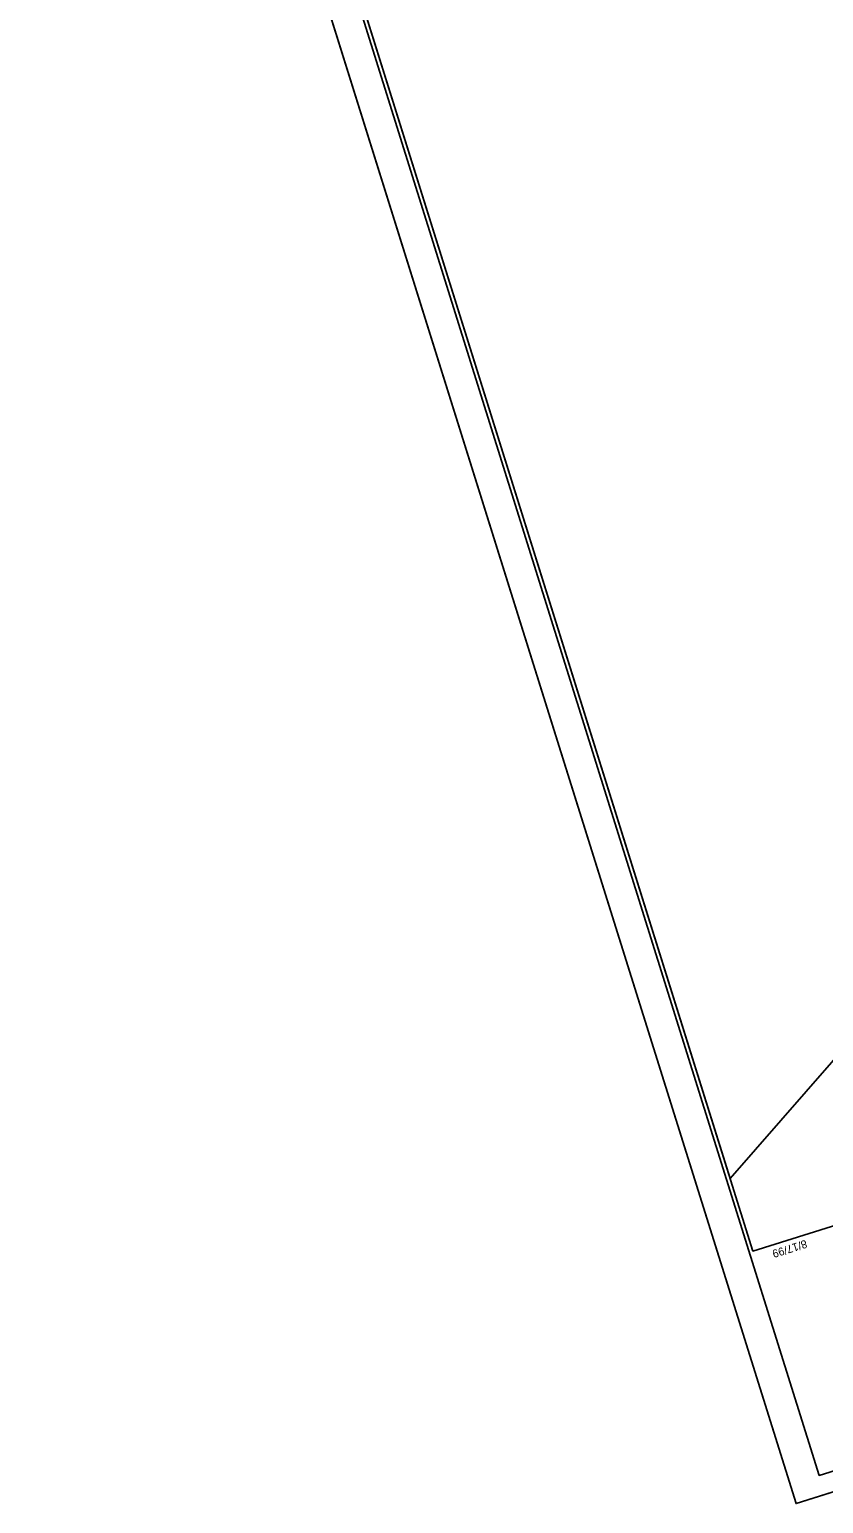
# Model space of a CAD drawing. Extents: x 473667 to 478950, y 494687 to 505998.
# Drawn here: x 473667 to 474189, y 504064 to 505031 of the extents above; entities that cross this region are included whole.
import ezdxf

# ---------------------------------------------------------------- set-up
doc = ezdxf.new("R2010")
doc.units = 0
for name, color, linetype in [('Sheet Cutting Line CELL', 7, 'Continuous'), ('Sheet Layout Plan Border', 7, 'Continuous'), ('Sheet Plan CELL', 7, 'Continuous'), ('Sheet Plan Layout CELL', 7, 'Continuous'), ('Sheet Plot Border Inside CELL', 7, 'Continuous'), ('Sheet Plot Border Outside CELL', 7, 'Continuous')]:
    doc.layers.add(name, color=color, linetype=linetype)

msp = doc.modelspace()

# ---------------------------------------------------------------- linework, layer by layer
at = {"layer": 'Sheet Cutting Line CELL'}
for p, q in [((473667.17, 505670.37), (474170.46, 504063.86)), ((474170.46, 504063.86), (475215.38, 504391.22))]:
    msp.add_line(p, q, dxfattribs=at)
at = {"layer": 'Sheet Layout Plan Border'}
msp.add_lwpolyline([(474406.84, 504597.01), (474903.65, 504485.25), (475129.18, 504591.08), (474710.64, 505927.06), (474746.68, 505812.01), (474670.33, 505788.09), (474619.34, 505950.85), (473859.33, 505712.76), (473919.13, 505521.87), (473753.52, 505469.97), (474127.2, 504277.17)], close=True, dxfattribs=at)
at = {"layer": 'Sheet Plan CELL'}
msp.add_line((474142.15, 504229.46), (474142.15, 504229.46), dxfattribs=at)
for points in [[(473693.71, 505660.9), (474142.15, 504229.46), (475144.13, 504543.36), (474695.69, 505974.78)], [(475144.13, 504543.36), (474142.18, 504229.44), (473753.51, 505469.97), (473896.7, 505514.84), (473836.91, 505705.74), (474695.69, 505974.78)]]:
    msp.add_lwpolyline(points, close=True, dxfattribs=at)
at = {"layer": 'Sheet Plan Layout CELL'}
msp.add_lwpolyline([(474142.18, 504229.44), (475144.13, 504543.36), (474695.7, 505974.76), (473895.53, 505724.09), (473967.06, 505495.78), (473765.24, 505432.55)], close=True, dxfattribs=at)
at = {"layer": 'Sheet Plot Border Inside CELL'}
msp.add_lwpolyline([(475192.41, 504397.64), (474694.35, 505987.44), (473687.6, 505672.06), (474185.66, 504082.25)], close=True, dxfattribs=at)
at = {"layer": 'Sheet Plot Border Outside CELL'}
msp.add_lwpolyline([(475215.38, 504391.22), (474712.1, 505997.73), (473667.17, 505670.37), (474170.46, 504063.86)], close=True, dxfattribs=at)

# ---------------------------------------------------------------- texts
at = {"layer": 'Sheet Plan CELL'}
msp.add_text('8/17/99', height=5.25, rotation=197.39476, dxfattribs=at).set_placement((474176.73, 504236.91))

doc.saveas('drawing.dxf')
